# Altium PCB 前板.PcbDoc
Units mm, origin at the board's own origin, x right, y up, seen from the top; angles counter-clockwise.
Board outline 60 x 60 mm, 4 copper layers (Top Layer, GND, PWR, Bottom Layer), stack 0.603 mm thick; 58 components, 58 nets, 327 pads, 79 vias.
Unrouted connection lines stored in the file: 2.
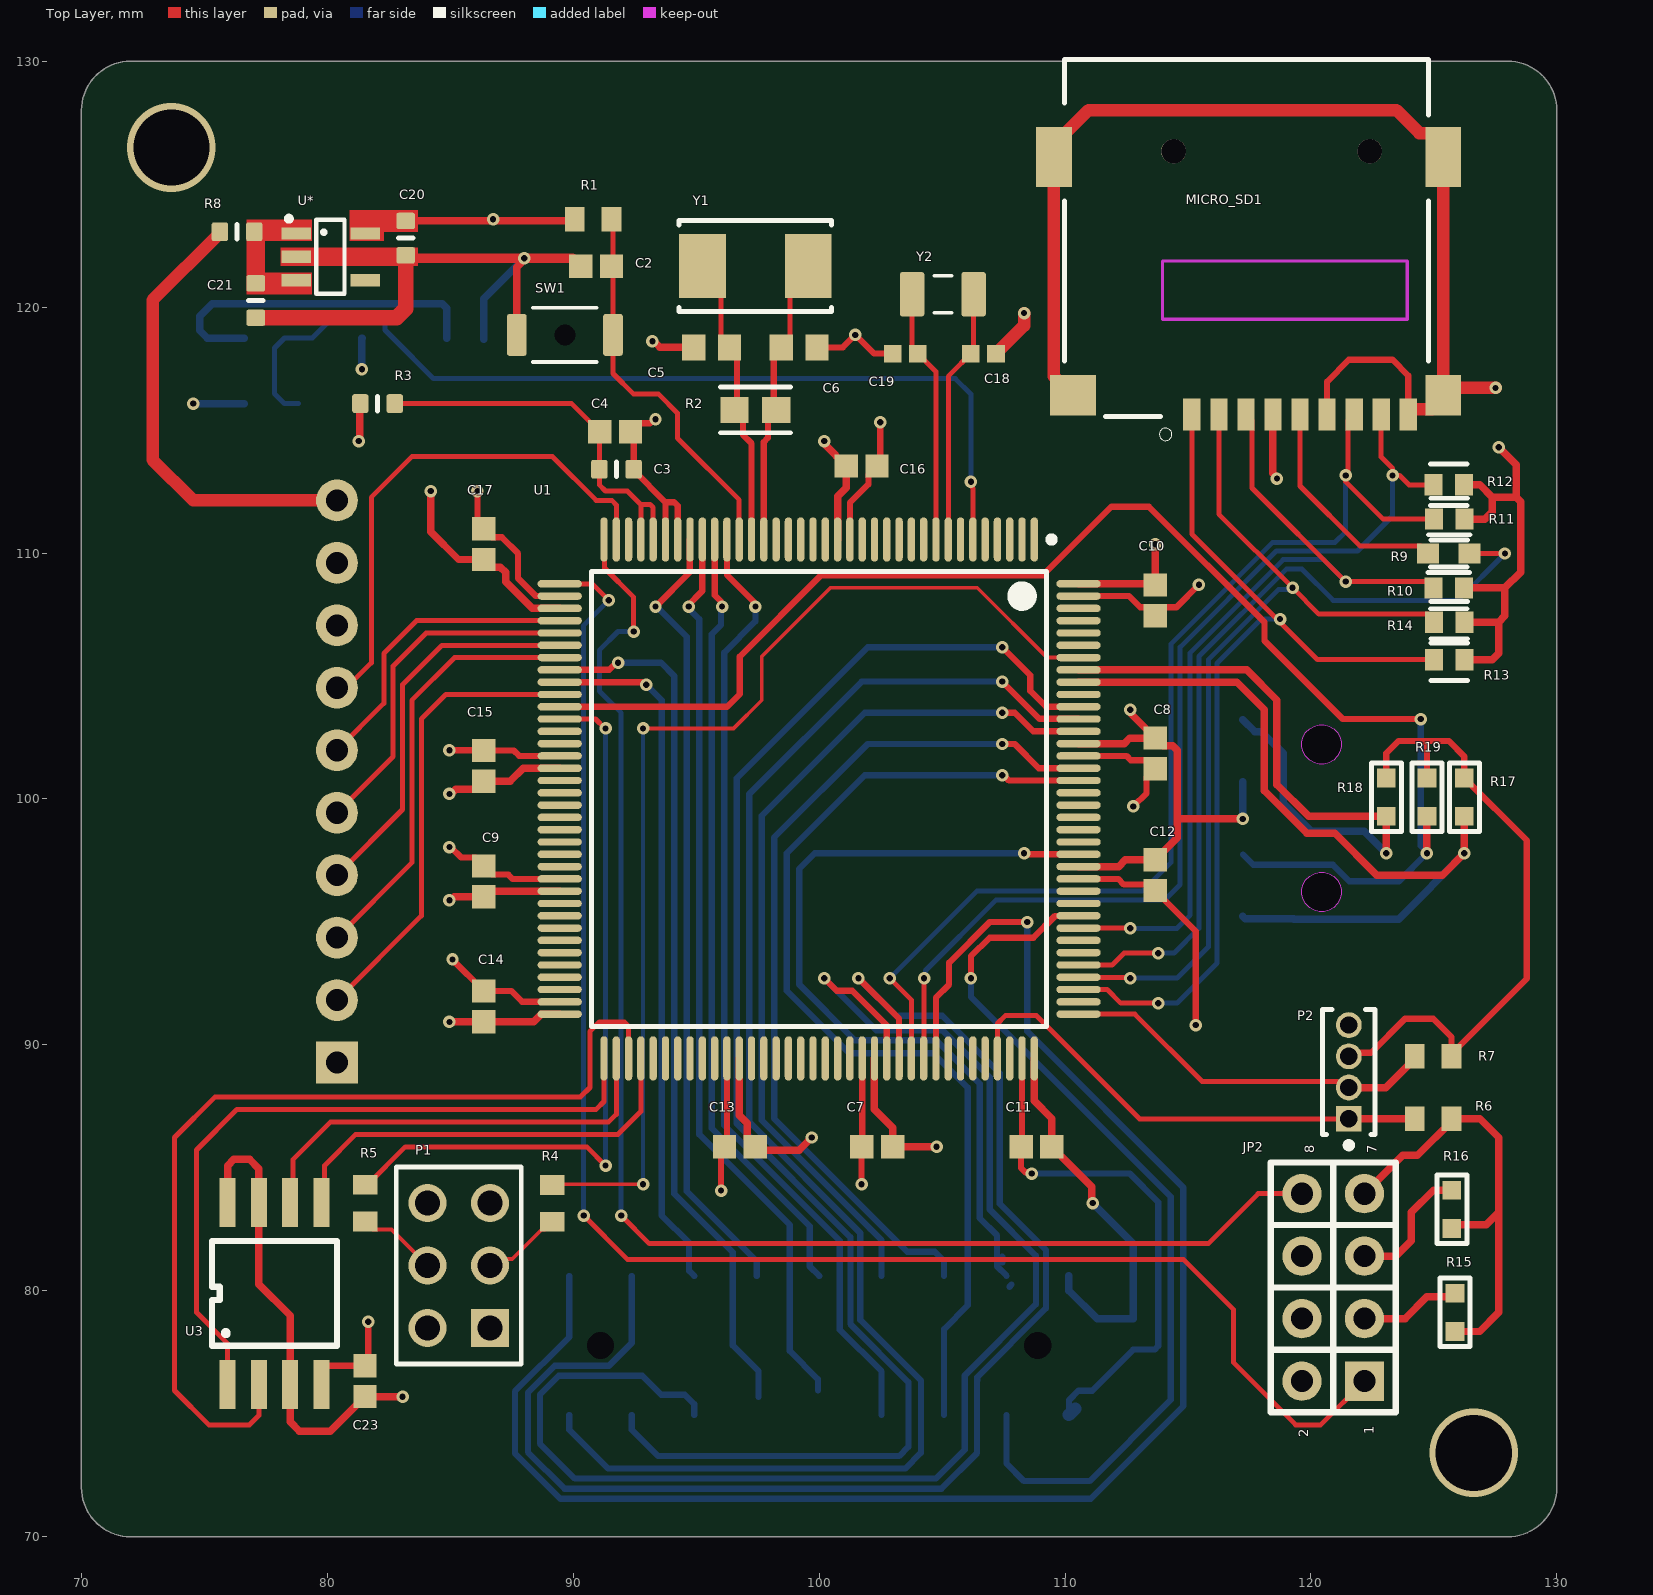
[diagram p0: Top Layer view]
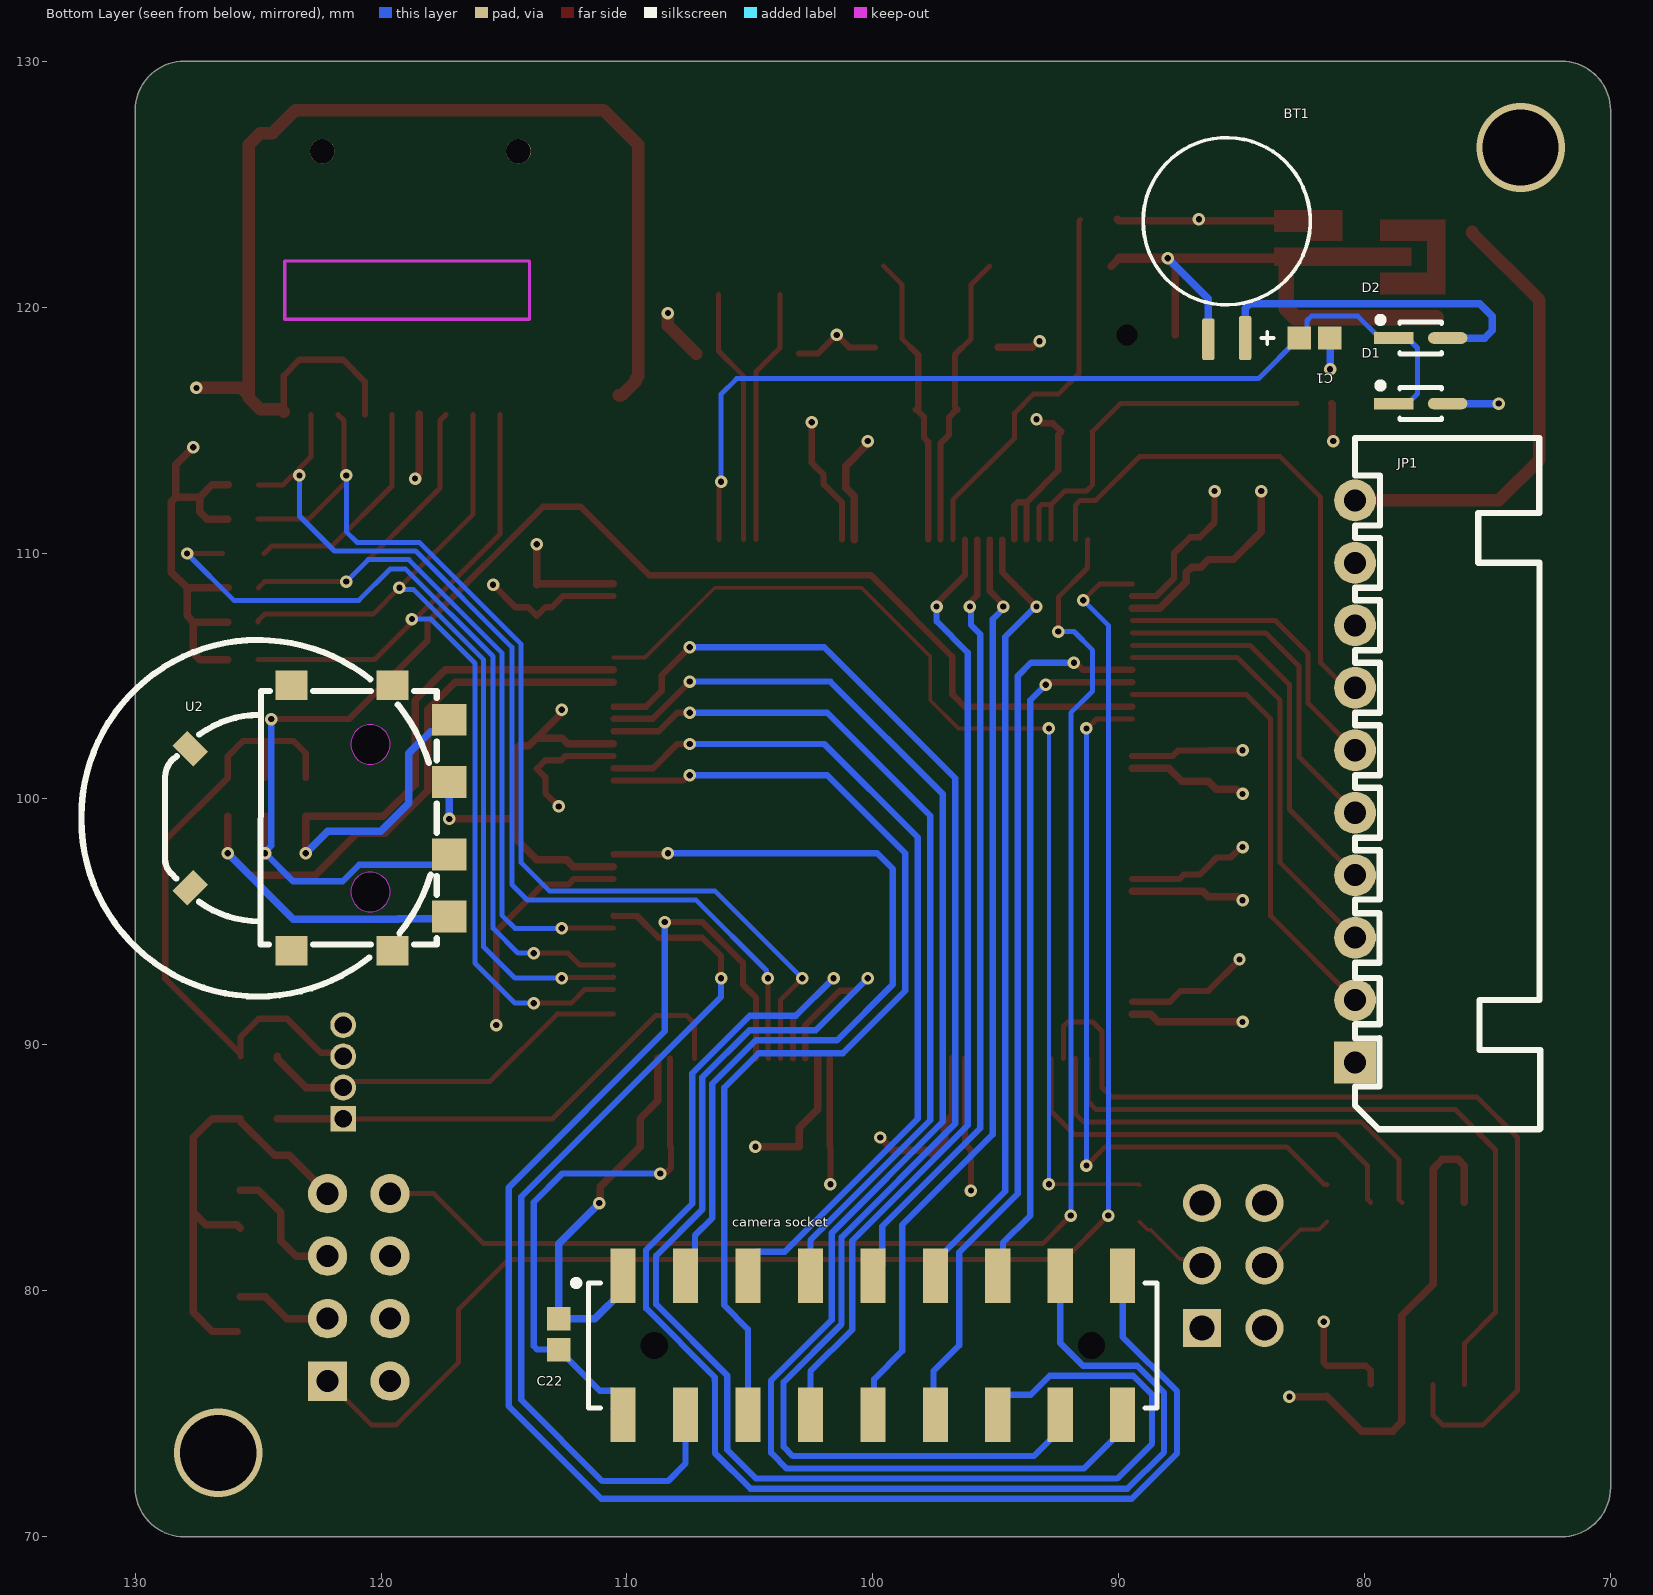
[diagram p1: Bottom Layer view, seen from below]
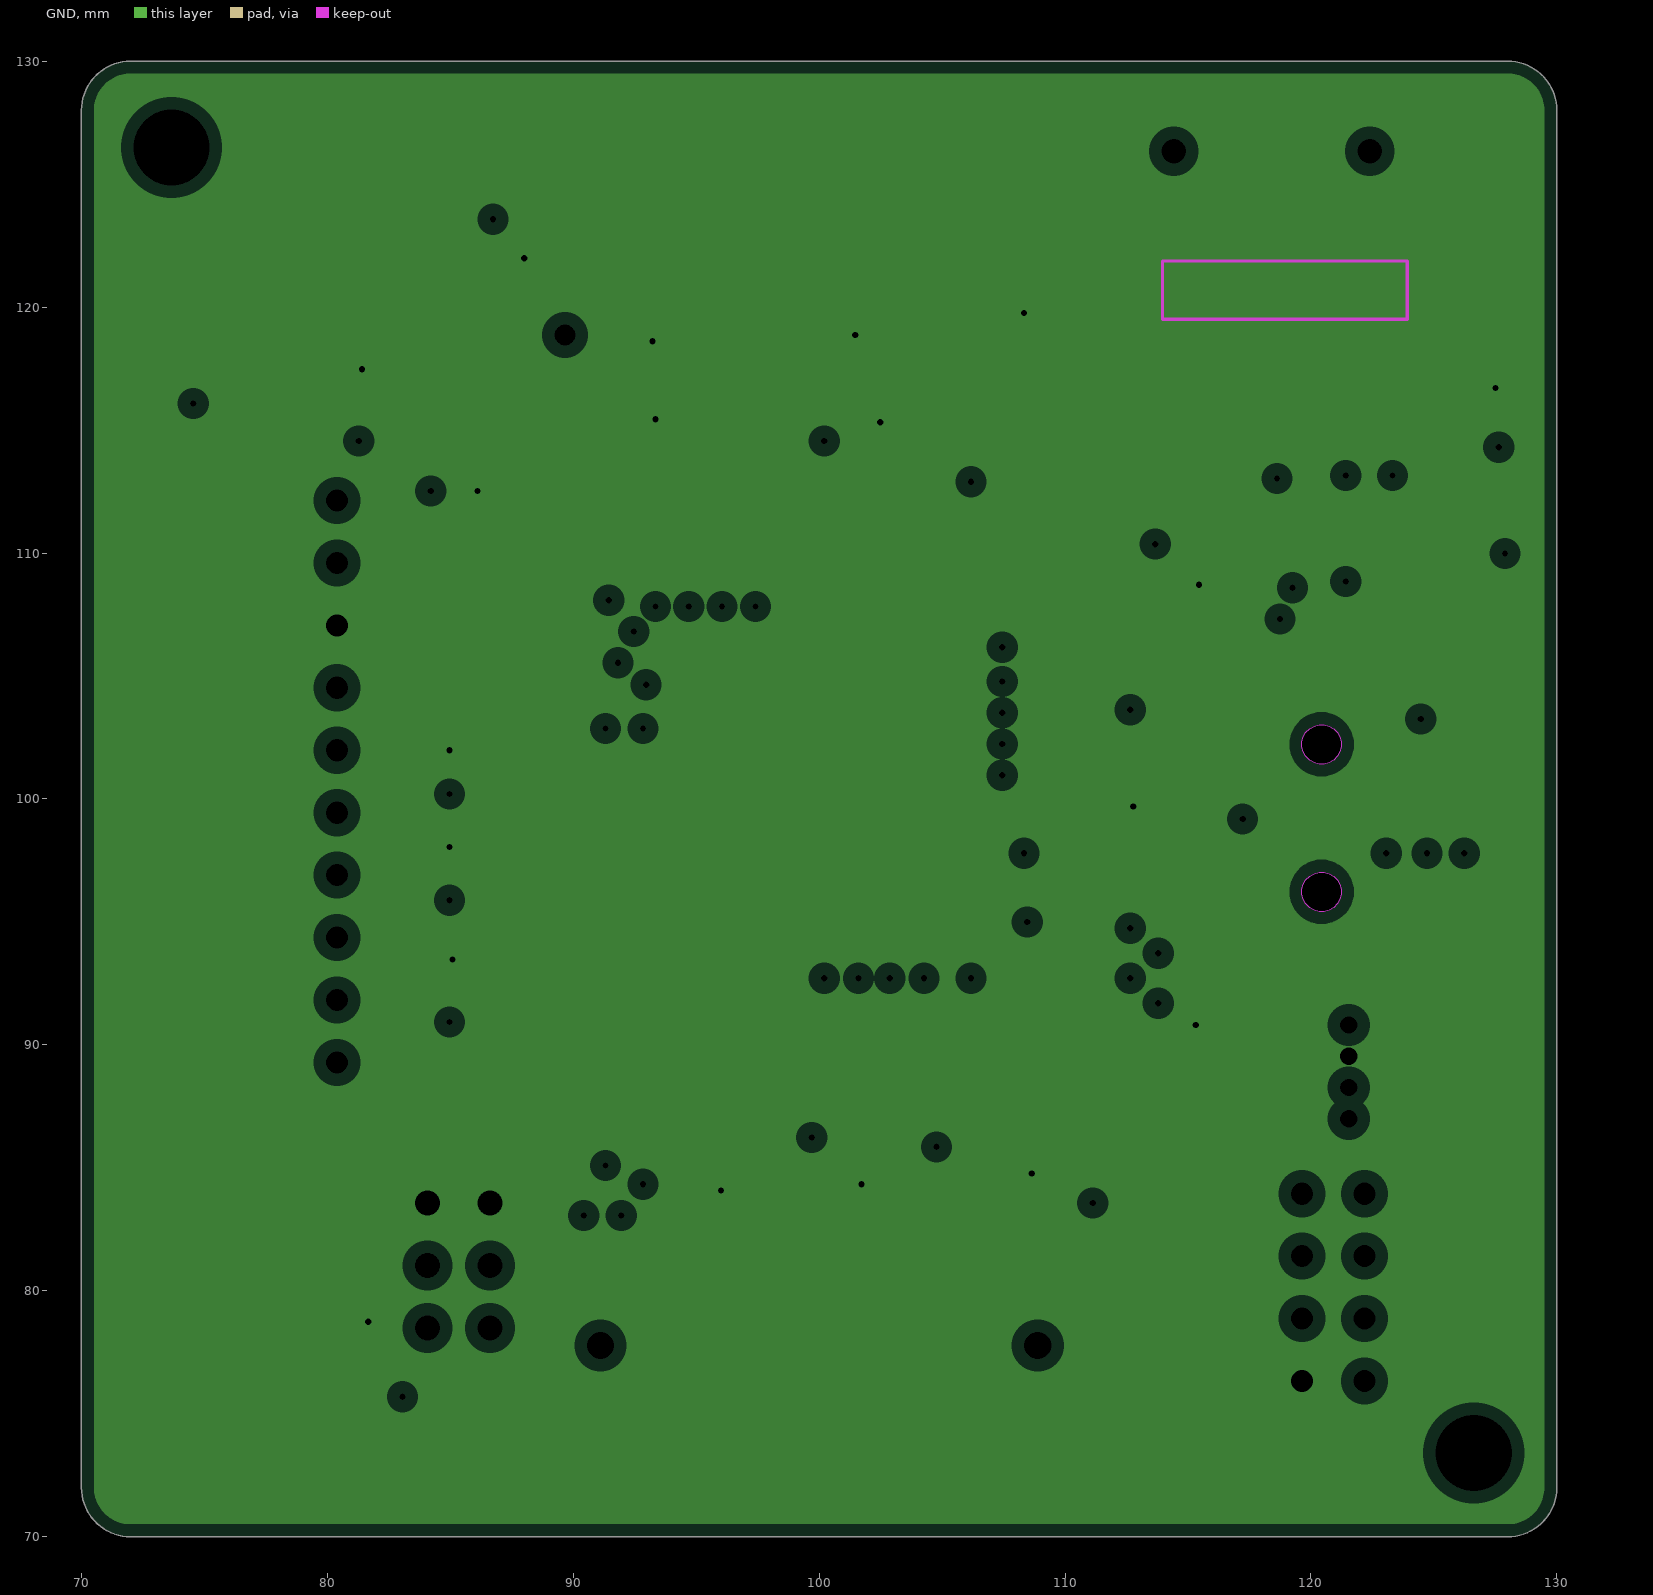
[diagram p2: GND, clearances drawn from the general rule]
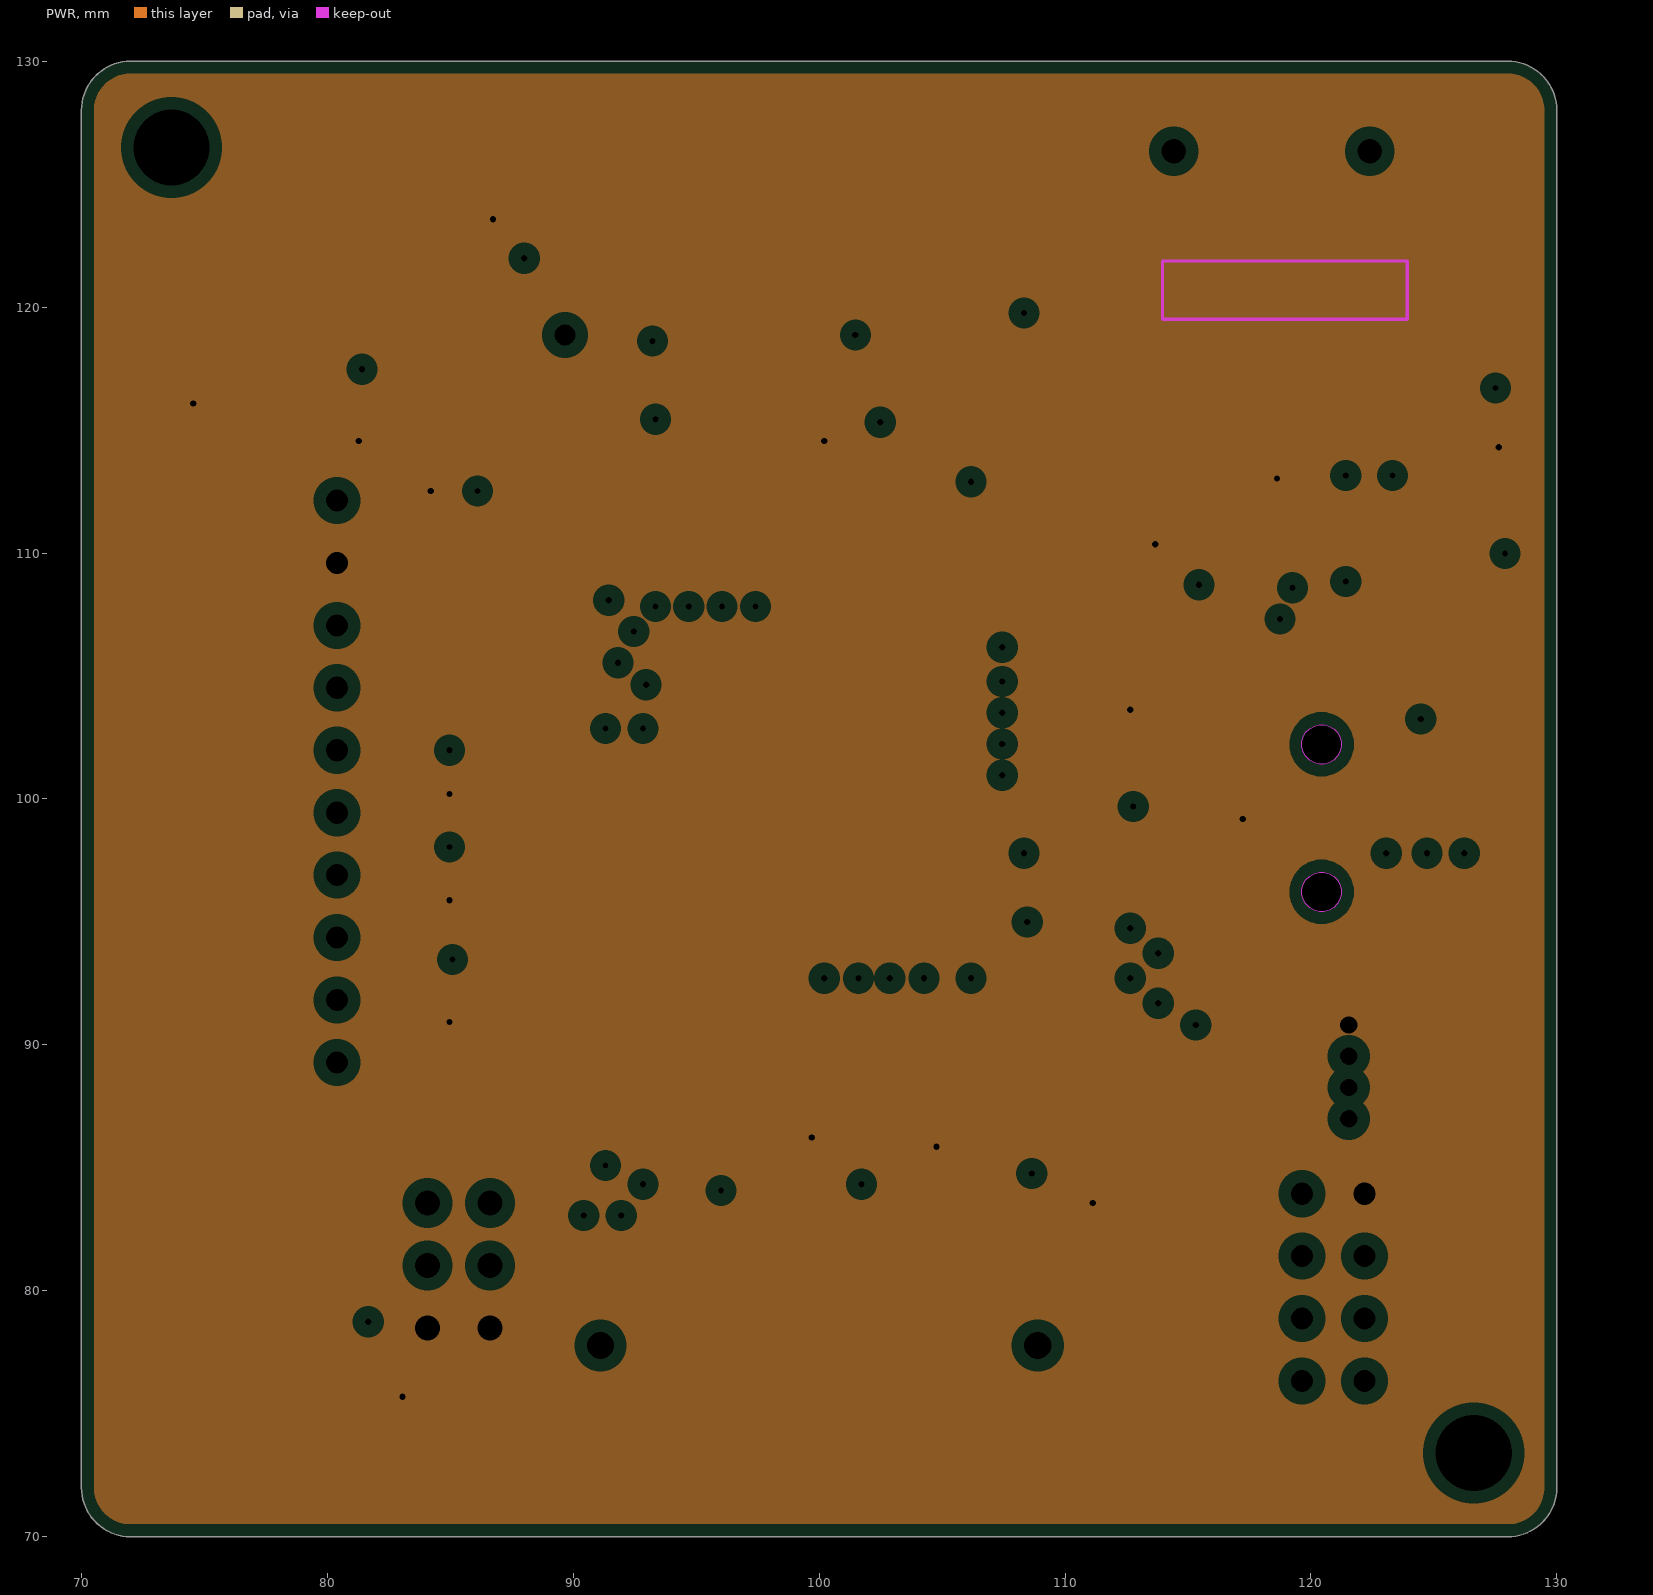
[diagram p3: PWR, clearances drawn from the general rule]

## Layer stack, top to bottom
Top Solder: solder mask 0.0102, Solder Resist, Dk 3.5
Top Layer: signal copper 0.0356
Dielectric 2: prepreg 0.0711, PP-006, Dk 4.1
GND: plane copper 0.035, net GND
Dielectric 1: dielectric 0.32, FR-4, Dk 4.8
PWR: plane copper 0.035, net VCC
Dielectric 3: prepreg 0.0711, PP-006, Dk 4.1
Bottom Layer: signal copper 0.0356
Bottom Solder: solder mask 0.0102, Solder Resist, Dk 3.5

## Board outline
70,72 70,128 cw(c72,128) 72,130 128,130 cw(c128,128) 130,128 130,72 cw(c128,72) 128,70 72,70 cw(c72,72)

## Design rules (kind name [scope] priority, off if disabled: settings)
Clearance Clearance_1 [InNetClass('pwr')] p1: gap=0.254 ignorepadtopadclearanceinfootprint=FALSE except(0.152: Arc-THPad Arc-Via Arc-Hole Track-THPad Track-Via Track-Hole SMDPad-SMDPad SMDPad-THPad SMDPad-Via SMDPad-Hole THPad-THPad THPad-Via THPad-Hole Via-Via Via-Hole Fill-Hole Poly-Hole Region-Hole Text-Hole)
Clearance [All] p2: gap=0.152 ignorepadtopadclearanceinfootprint=FALSE
DiffPairsRouting DiffPair_DiffPairsRouting [InDifferentialPair ('NewDifferentialPair2')] p1: maxlimit=0.254 minlimit=0.254 mostfreqgap=0.254 toplayer_minwidth=0.152 toplayer_maxwidth=0.381 toplayer_prefwidth=0.203 bottomlayer_minwidth=0.152 bottomlayer_maxwidth=0.381 bottomlayer_prefwidth=0.203 maxuncoupledlength=12.7
DiffPairsRouting DiffPair_DiffPairsRouting_1 [InDifferentialPair ('NewDifferentialPair1')] p2 off: maxlimit=0.254 minlimit=0.254 mostfreqgap=0.254 toplayer_minwidth=0.152 toplayer_maxwidth=0.381 toplayer_prefwidth=0.254 bottomlayer_minwidth=0.152 bottomlayer_maxwidth=0.381 bottomlayer_prefwidth=0.254 maxuncoupledlength=12.7
DiffPairsRouting [All] p3: maxlimit=0.254 minlimit=0.254 mostfreqgap=0.254 toplayer_minwidth=0.381 toplayer_maxwidth=0.381 toplayer_prefwidth=0.381 bottomlayer_minwidth=0.381 bottomlayer_maxwidth=0.381 bottomlayer_prefwidth=0.381 maxuncoupledlength=12.7
MatchedLengths DiffPair_MatchedLengths [InDifferentialPair ('NewDifferentialPair2')] p1: tolerance=25.4 checknetsindiffpair=FALSE checkdiffpairvsdiffpair=TRUE checkxsignals=TRUE checkothers=TRUE
MatchedLengths DiffPair_MatchedLengths_1 [InDifferentialPair ('NewDifferentialPair1')] p2: tolerance=25.4 checknetsindiffpair=FALSE checkdiffpairvsdiffpair=TRUE checkxsignals=TRUE checkothers=TRUE
PlaneClearance [All] p1: clearance=0.508
PlaneConnect [All] p1: planeconnectstyle=Relief reliefexpansion=0.508 reliefentries=4 reliefconductorwidth=0.254 reliefairgap=0.254
PolygonConnect [All] p1: connectstyle=Relief reliefconductorwidth=0.254 reliefentries=4 polygonreliefangle="90 Angle" airgapwidth=0.254
RoutingVias [All] p1: holewidth=0.254 width=0.508 viastyle="Through Hole" minholewidth=0.254 minwidth=0.508 maxholewidth=0.711 maxwidth=1.27
SolderMaskExpansion [All] p1: expansion=0.102 istentingtop=FALSE
Width pwr [InNetClass('pwr')] p1: maxlimit=1.27 minlimit=0.254 preferedwidth=0.635
Width [All] p2: maxlimit=12.7 minlimit=0.152 preferedwidth=0.381
27 further rules are at their usual default settings.

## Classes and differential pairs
pad class stm_pad: U1-1 U1-2 U1-3 U1-4 U1-5 U1-6 U1-7 U1-8 U1-9 U1-10 U1-11 U1-12 U1-13 U1-14 U1-15 U1-16 U1-17 U1-18 U1-19 U1-20 U1-21 U1-22 U1-23 U1-24 U1-25 U1-26 U1-27 U1-28 U1-29 U1-30 U1-31 U1-32 U1-33 U1-34 U1-35 U1-36 U1-37 U1-38 U1-39 U1-40 U1-41 U1-42 U1-43 U1-44 U1-45 U1-46 U1-47 U1-48 U1-49 U1-50 U1-51 U1-52 U1-53 U1-54 U1-55 U1-56 U1-57 U1-58 U1-59 U1-60 U1-61 U1-62 U1-63 U1-64 U1-65 U1-66 U1-67 U1-68 U1-69 U1-70 U1-71 U1-72 U1-73 U1-74 U1-75 U1-76 U1-77 U1-78 U1-79 U1-80 U1-81 U1-82 U1-83 U1-84 U1-85 U1-86 U1-87 U1-88 U1-89 U1-90 U1-91 U1-92 U1-93 U1-94 U1-95 U1-96 U1-97 U1-98 U1-99 U1-100 U1-101 U1-102 U1-103 U1-104 U1-105 U1-106 U1-107 U1-108 U1-109 U1-110 U1-111 U1-112 U1-113 U1-114 U1-115 U1-116 U1-117 U1-118 U1-119 U1-120 U1-121 U1-122 U1-123 U1-124 U1-125 U1-126 U1-127 U1-128 U1-129 U1-130 U1-131 U1-132 U1-133 U1-134 U1-135 U1-136 U1-137 U1-138 U1-139 U1-140 U1-141 U1-142 U1-143 U1-144

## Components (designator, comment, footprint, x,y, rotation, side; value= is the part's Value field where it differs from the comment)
BT1 "MS621FE-FL11E" SEIK-MS621FE-FL11E-2_V 85.61,123.495 r270 bottom
C1 "Capacitor 100 nF +/-10% 50 V 0603" CAPC1608X90X40NL10T20 82.042,118.745 r0 bottom value=100nF
C2 "Capacitor 100 nF +/-10% 50 V 0603" CAPC1608X90X40NL10T20 90.932,121.666 r0 top value=100nF
C3 "Capacitor 10µF +/-20% 10V 0603" CAPC0603(1608)100_L 91.759,113.411 r0 top value=10µF
C4 "Capacitor 100 nF +/-10% 50 V 0603" CAPC1608X90X40NL10T20 91.704,114.935 r0 top value=100nF
C5 "GRM1885C1H220JA01D" CAPC1608X90X35ML10T15 95.631,118.364 r0 top value=22pF
C6 "GRM1885C1H220JA01D" CAPC1608X90X35ML10T15 99.187,118.364 r180 top value=22pF
C7 "Capacitor 100 nF +/-10% 50 V 0603" CAPC1608X90X40NL10T20 102.362,85.852 r0 top value=100nF
C8 "Capacitor 100 nF +/-10% 50 V 0603" CAPC1608X90X40NL10T20 113.665,101.854 r90 top value=100nF
C9 "Capacitor 100 nF +/-10% 50 V 0603" CAPC1608X90X40NL10T20 86.36,96.647 r270 top value=100nF
C10 "Capacitor 100 nF +/-10% 50 V 0603" CAPC1608X90X40NL10T20 113.665,108.077 r90 top value=100nF
C11 "Capacitor 100 nF +/-10% 50 V 0603" CAPC1608X90X40NL10T20 108.839,85.852 r0 top value=100nF
C12 "Capacitor 100 nF +/-10% 50 V 0603" CAPC1608X90X40NL10T20 113.665,96.901 r90 top value=100nF
C13 "Capacitor 100 nF +/-10% 50 V 0603" CAPC1608X90X40NL10T20 96.774,85.852 r0 top value=100nF
C14 "Capacitor 100 nF +/-10% 50 V 0603" CAPC1608X90X40NL10T20 86.36,91.567 r270 top value=100nF
C15 "Capacitor 100 nF +/-10% 50 V 0603" CAPC1608X90X40NL10T20 86.36,101.346 r270 top value=100nF
C16 "Capacitor 100 nF +/-10% 50 V 0603" CAPC1608X90X40NL10T20 101.727,113.538 r180 top value=100nF
C17 "Capacitor 100 nF +/-10% 50 V 0603" CAPC1608X90X40NL10T20 86.36,110.363 r270 top value=100nF
C18 "Capacitor 10 pF +/- 5% 50 V 0402" CAPC1005X55X25ML05T05 106.68,118.11 r180 top value=10pF
C19 "Capacitor 10 pF +/- 5% 50 V 0402" CAPC1005X55X25ML05T05 103.505,118.11 r0 top value=10pF
C20 "Capacitor 10µF +/-20% 10V 0603" CAPC0603(1608)100_L 83.185,122.809 r90 top value=10µF
C21 "Capacitor 10µF +/-20% 10V 0603" CAPC0603(1608)100_L 77.089,120.269 r270 top value=10µF
C22 "Capacitor 100 nF +/-10% 50 V 0603" CAPC1608X90X40NL10T20 112.776,78.232 r270 bottom value=100nF
C23 "Capacitor 100 nF +/-10% 50 V 0603" CAPC1608X90X40NL10T20 81.534,76.327 r270 top value=100nF
"camera socket" "SSM-109-S-DV-A" SMTC-SSM-109-X-DV-A 100,77.778 r180 bottom
D1 "1N4148WS" FP-477AB-IPC_A 77.724,116.078 r180 bottom
D2 "1N4148WS" FP-477AB-IPC_A 77.724,118.745 r180 bottom
JP1 "10p" XH2.54-WI-10P 80.391,100.711 r90 bottom
JP2 "2.54排针排母 4X2" HDR2.54-LI-2x4P 120.904,80.137 r90 top
MICRO_SD1 "TF-01A" TF-01A 117.386,122.811 r180 top
P1 "TSW-103-08-T-D" SMTC-TSW-103-08-X-D 86.614,78.486 r90 top
P2 "GRPB041VWVN-RC" SLIN-GRPB041VWVN-RC_V 121.539,88.9 r90 top
R1 "Resistor 10k +/-1% 0603 100 mW" RESC1608X55X25ML10T15 90.805,123.571 r0 top value=10k
R2 "ERJ-3EKF1004V" FP-ERJ3EK-IPC_A 97.409,115.824 r0 top value=1M
R3 "ERJ3EKF10R0V" RESC0603(1608)_L 82.042,116.078 r180 top value=10
R4 "Resistor 10k +/-1% 0603 100 mW" RESC1608X55X25ML10T15 89.154,83.554 r270 top value=10k
R5 "Resistor 10k +/-1% 0603 100 mW" RESC1608X55X25ML10T15 81.534,83.566 r90 top value=10k
R6 "Resistor 10k +/-1% 0603 100 mW" RESC1608X55X25ML10T15 124.968,86.995 r0 top value=10k
R7 "Resistor 10k +/-1% 0603 100 mW" RESC1608X55X25ML10T15 124.968,89.535 r0 top value=10k
R8 "0R3J" RESC0603(1608)_L 76.327,123.063 r0 top value=0
R9 "RC0603JR-07100RL" FP-RC0603-0_55-MFG 125.603,109.982 r180 top value=100
R10 "CRCW060347K0FKEA" FP-CRCW0603-e3-IPC_C 125.603,108.585 r180 top value=47k
R11 "CRCW060347K0FKEA" FP-CRCW0603-e3-IPC_C 125.623,111.379 r180 top value=47k
R12 "CRCW060347K0FKEA" FP-CRCW0603-e3-IPC_C 125.603,112.776 r180 top value=47k
R13 "CRCW060347K0FKEA" FP-CRCW0603-e3-IPC_C 125.623,105.664 r180 top value=47k
R14 "CRCW060347K0FKEA" FP-CRCW0603-e3-IPC_C 125.623,107.188 r180 top value=47k
R15 "10k" "R 0603_L" 125.857,79.121 r90 top
R16 "10k" "R 0603_L" 125.73,83.312 r90 top
R17 "10k" "R 0603_L" 126.238,100.076 r270 top
R18 "10k" "R 0603_L" 123.063,100.076 r90 top
R19 "10k" "R 0603_L" 124.714,100.076 r270 top
SW1 "B3U-1000P-B" OMRON-B3U-1000P-2-B_V 89.662,118.872 r180 top
U1 "STM32F103ZET6" STM-LQFP144_N 100,100 r270 top
U2 "SIQ-02FVS3" SW-SMD_SIQ-02FVS3_1 122.498,99.221 r90 bottom
U3 "W25Q128FVSIG" SOIC-8_208mil 77.978,79.883 r90 top
U* "ME6211C33M5G-N" SOT23-5N 80.137,122.047 r270 top
Y1 "ABM7-8.000MHZ-D2Y-T" FP-ABM7-MFG 97.409,121.666 r0 top
Y2 "ABS07-166-32.768KHZ-T" EPSON-FC-135_V 105.029,120.523 r180 top

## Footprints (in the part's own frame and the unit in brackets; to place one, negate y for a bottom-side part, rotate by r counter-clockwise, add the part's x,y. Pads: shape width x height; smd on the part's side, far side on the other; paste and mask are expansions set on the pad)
CAPC0603(1608)100_L [mm] "Chip Capacitor, Body 1.6x0.8mm, Height 1.0mm, IPC High Density"
  rrect25% 0.66x0.76 smd: 1(-0.7,0) 2(0.7,0)
  silkscreen extent 0,-0.3 0,0.3, body extent -0.8,-0.4 0.8,0.4, height 0.95
CAPC1005X55X25ML05T05 [mm] "Chip Capacitor, 2-Leads, Body 1.05x0.55mm, IPC Low Density"
  rect 0.72x0.72 smd: 1(-0.51,0) 2(0.51,0)
  body extent -0.53,-0.28 0.53,0.28, height 0.55
CAPC1608X90X35ML10T15 [mm] "Chip Capacitor, 2-Leads, Body 1.7x0.9mm, IPC Low Density"
  rect 0.95x1.05 smd: 1(-0.725,0) 2(0.725,0)
  body extent -0.85,-0.45 0.85,0.45, height 0.9
CAPC1608X90X40NL10T20 [mm] "Chip Capacitor, 2-Leads, Body 1.70x0.90mm, IPC Medium Density"
  rect 0.95x0.95 smd: 1(-0.625,0) 2(0.625,0)
  body extent -0.85,-0.45 0.85,0.45, height 0.9
EPSON-FC-135_V [mm] "SMD, 2-Leads, Body 3.2x1.5mm"
  rrect20% 1x1.8 smd: 1(-1.25,0) 2(1.25,0)
  silkscreen extent -0.35,-0.75 0.35,0.75, body extent -1.6,-0.75 1.6,0.75, height 0.9
FP-477AB-IPC_A [mm]
  rect 1.606x0.472 smd paste+0 mask+0: 1(-1.1,0)
  rrect100% 1.606x0.472 smd paste+0 mask+0: 2(1.1,0)
  silkscreen extent -1.76,-0.65 0.85,0.86, body extent -1.25,-0.63 1.25,0.63, height 0.9
FP-ABM7-MFG [mm]
  rect 1.9x2.6 smd paste+0 mask+0: 1(-2.15,0) 2(2.15,0)
  silkscreen extent -3.1,-1.85 3.1,1.85, body extent -3.2,-1.95 3.2,1.95, height 0.25
FP-CRCW0603-e3-IPC_C [mm]
  rect 0.735x0.862 smd paste+0 mask+0: 1(-0.615,0) 2(0.615,0)
  silkscreen extent -0.75,-0.85 0.75,0.85, body extent -0.77,-0.43 0.77,0.43, height 0.5
FP-ERJ3EK-IPC_A [mil]
  rect 45.53x41.82 smd paste+0 mask+0: 1(-33.5,0) 2(33.5,0)
  silkscreen extent -56,-37 56,37, body extent -76,-41 76,41, height 10
FP-RC0603-0_55-MFG [mm]
  rect 0.9x0.8 smd paste+0 mask+0: 1(-0.85,0) 2(0.85,0)
  silkscreen extent -0.87,-0.76 0.85,0.77, body extent -0.8,-0.4 0.8,0.4, height 0.55
HDR2.54-LI-2x4P [mm] "双排排针，4x2脚"
  rect 1.6x1.6 hole 0.9: 1(-3.81,-1.27)
  round 1.6 hole 0.9: 2(-3.81,1.27) 3(-1.27,-1.27) 4(-1.27,1.27) 5(1.27,-1.27) 6(1.27,1.27) 7(3.81,-1.27) 8(3.81,1.27)
  silkscreen extent -5.08,-2.54 5.08,2.54, body extent -5.08,-2.54 5.08,2.54, height 8.5
OMRON-B3U-1000P-2-B_V [mm] "SMT, 2-Leads, Body 3x2.5mm"
  rrect25% 0.8x1.7 smd: 1(-1.954,0) 2(1.954,0)
  round 0 hole 0.85 unplated: H1(0,0)
  silkscreen extent -1.3,-1.1 1.3,1.1, body extent -2,-1.25 2,1.25, height 1.6
"R 0603_L" [mil] "1/10W贴片电阻"
  rect 30x30 smd: 1(-30.59,0) 2(30.59,0)
  silkscreen extent -55,-24 55,24, body extent -31,-16 32,16, height 16
RESC0603(1608)_L [mm] "Chip Resistor, Body 1.6x0.8mm, IPC High Density"
  rrect25% 0.66x0.76 smd: 1(-0.7,0) 2(0.7,0)
  silkscreen extent 0,-0.3 0,0.3, body extent -0.8,-0.4 0.8,0.4, height 0.45
RESC1608X55X25ML10T15 [mm] "Chip Resistor, 2-Leads, Body 1.70x0.90mm, IPC Low Density"
  rect 0.8x1 smd: 1(-0.75,0) 2(0.75,0)
  body extent -0.85,-0.45 0.85,0.45, height 0.55
SEIK-MS621FE-FL11E-2_V [mm] "SMD, 2-Leads, Diameter 6.8mm"
  rrect35% 1.8x0.5 smd: 1(4.75,0.75)
  rrect35% 1.7x0.5 smd: 2(4.8,-0.75)
  silkscreen extent -3.4,-3.4 5,3.4, body extent -3.4,-3.4 4.35,3.4, height 2.7
SLIN-GRPB041VWVN-RC_V [mm] "Header, 4-Leads, Body 5.08x2.14mm, Pitch 1.27mm"
  rect 1.05x1.05 hole 0.7: 1(-1.905,0)
  round 1.05 hole 0.7: 2(-0.635,0) 3(0.635,0) 4(1.905,0)
  silkscreen extent -3.1,-1.07 2.54,1.07, body extent -2.54,-1.07 2.54,1.07, height 4
SMTC-SSM-109-X-DV-A [mm] "C.L. Double Vertical SMT Socket Strip, 2x9 Pins, 2.54mm Pitch, Female"
  rect 1.02x2.22 smd: 1(-10.16,2.825) 2(-10.16,-2.825) 3(-7.62,2.825) 4(-7.62,-2.825) 5(-5.08,2.825) 6(-5.08,-2.825) 7(-2.54,2.825) 8(-2.54,-2.825) 9(0,2.825) 10(0,-2.825) 11(2.54,2.825) 12(2.54,-2.825) 13(5.08,2.825) 14(5.08,-2.825) 15(7.62,2.825) 16(7.62,-2.825) 17(10.16,2.825) 18(10.16,-2.825)
  round 0.8 hole 1.1 unplated: MH1(-8.89,0) MH2(8.89,0)
  silkscreen extent -12.19,-2.54 11.56,2.66, body extent -11.43,-3.52 11.43,3.52, height 7.42
SMTC-TSW-103-08-X-D [mm] ".025 SQ Post Terminal Strip Assembly, 2x3 Pins, Vertical, 2.54mm Pitch, Male"
  rect 1.55x1.55 hole 1.02: 1(0,0)
  round 1.55 hole 1.02: 2(0,2.54) 3(2.54,0) 4(2.54,2.54) 5(5.08,0) 6(5.08,2.54)
  silkscreen extent -1.46,-1.27 6.54,3.81, body extent -1.27,-1.27 6.35,3.81, height 8.38
SOIC-8_208mil [mm]
  rect 2x0.65 smd: 1(-3.688,2.032) 2(-3.688,0.762) 3(-3.688,-0.508) 4(-3.688,-1.778) 5(3.712,-1.778) 6(3.712,-0.508) 7(3.712,0.762) 8(3.712,2.032)
  silkscreen extent -2.12,-2.41 2.14,2.67, body extent -4.2,-2.56 4.2,2.82, height 2.3
SOT23-5N [mm] "3x1.6x1.1mm(长宽高)"
  rect 0.5x1.2 smd: 1(-0.95,-1.4) 2(0,-1.4) 3(0.95,-1.4) 4(0.95,1.4) 5(-0.95,1.4)
  silkscreen extent -1.63,-1.78 1.5,0.56, body extent -1.5,-1.4 1.5,1.4, height 1.15
STM-LQFP144_N [mm] "Thin QFP, 144-Leads, Body 20x20mm, Pitch 0.5mm, IPC Medium Density"
  oval 1.8x0.3 smd: 1(-10.55,8.75) 2(-10.55,8.25) 3(-10.55,7.75) 4(-10.55,7.25) 5(-10.55,6.75) 6(-10.55,6.25) 7(-10.55,5.75) 8(-10.55,5.25) 9(-10.55,4.75) 10(-10.55,4.25) 11(-10.55,3.75) 12(-10.55,3.25) 13(-10.55,2.75) 14(-10.55,2.25) 15(-10.55,1.75) 16(-10.55,1.25) 17(-10.55,0.75) 18(-10.55,0.25) 19(-10.55,-0.25) 20(-10.55,-0.75) 21(-10.55,-1.25) 22(-10.55,-1.75) 23(-10.55,-2.25) 24(-10.55,-2.75) 25(-10.55,-3.25) 26(-10.55,-3.75) 27(-10.55,-4.25) 28(-10.55,-4.75) 29(-10.55,-5.25) 30(-10.55,-5.75) 31(-10.55,-6.25) 32(-10.55,-6.75) 33(-10.55,-7.25) 34(-10.55,-7.75) 35(-10.55,-8.25) 36(-10.55,-8.75) 73(10.55,-8.75) 74(10.55,-8.25) 75(10.55,-7.75) 76(10.55,-7.25) 77(10.55,-6.75) 78(10.55,-6.25) 79(10.55,-5.75) 80(10.55,-5.25) 81(10.55,-4.75) 82(10.55,-4.25) 83(10.55,-3.75) 84(10.55,-3.25) 85(10.55,-2.75) 86(10.55,-2.25) 87(10.55,-1.75) 88(10.55,-1.25) 89(10.55,-0.75) 90(10.55,-0.25) 91(10.55,0.25) 92(10.55,0.75) 93(10.55,1.25) 94(10.55,1.75) 95(10.55,2.25) 96(10.55,2.75) 97(10.55,3.25) 98(10.55,3.75) 99(10.55,4.25) 100(10.55,4.75) 101(10.55,5.25) 102(10.55,5.75) 103(10.55,6.25) 104(10.55,6.75) 105(10.55,7.25) 106(10.55,7.75) 107(10.55,8.25) 108(10.55,8.75)
  oval 0.3x1.8 smd: 37(-8.75,-10.55) 38(-8.25,-10.55) 39(-7.75,-10.55) 40(-7.25,-10.55) 41(-6.75,-10.55) 42(-6.25,-10.55) 43(-5.75,-10.55) 44(-5.25,-10.55) 45(-4.75,-10.55) 46(-4.25,-10.55) 47(-3.75,-10.55) 48(-3.25,-10.55) 49(-2.75,-10.55) 50(-2.25,-10.55) 51(-1.75,-10.55) 52(-1.25,-10.55) 53(-0.75,-10.55) 54(-0.25,-10.55) 55(0.25,-10.55) 56(0.75,-10.55) 57(1.25,-10.55) 58(1.75,-10.55) 59(2.25,-10.55) 60(2.75,-10.55) 61(3.25,-10.55) 62(3.75,-10.55) 63(4.25,-10.55) 64(4.75,-10.55) 65(5.25,-10.55) 66(5.75,-10.55) 67(6.25,-10.55) 68(6.75,-10.55) 69(7.25,-10.55) 70(7.75,-10.55) 71(8.25,-10.55) 72(8.75,-10.55) 109(8.75,10.55) 110(8.25,10.55) 111(7.75,10.55) 112(7.25,10.55) 113(6.75,10.55) 114(6.25,10.55) 115(5.75,10.55) 116(5.25,10.55) 117(4.75,10.55) 118(4.25,10.55) 119(3.75,10.55) 120(3.25,10.55) 121(2.75,10.55) 122(2.25,10.55) 123(1.75,10.55) 124(1.25,10.55) 125(0.75,10.55) 126(0.25,10.55) 127(-0.25,10.55) 128(-0.75,10.55) 129(-1.25,10.55) 130(-1.75,10.55) 131(-2.25,10.55) 132(-2.75,10.55) 133(-3.25,10.55) 134(-3.75,10.55) 135(-4.25,10.55) 136(-4.75,10.55) 137(-5.25,10.55) 138(-5.75,10.55) 139(-6.25,10.55) 140(-6.75,10.55) 141(-7.25,10.55) 142(-7.75,10.55) 143(-8.25,10.55) 144(-8.75,10.55)
  silkscreen extent -10.67,-9.25 9.25,9.58, body extent -10,-10 10,10, height 1.6
SW-SMD_SIQ-02FVS3_1 [mm]
  rect 1.2x1.3 smd paste+0 mask+0.05: 1(5.4,-2.964) 2(5.4,1.136) 5(-5.4,1.136) 6(-5.4,-2.964)
  rect 0.85x1.2 smd rot 135 paste+0 mask+0.05: 3(2.828,5.264)
  rect 0.85x1.2 smd rot 45 paste+0 mask+0.05: 4(-2.828,5.264)
  rect 1.3x1.4 smd paste+0 mask+0.05: A(-4,-5.264) B(4,-5.264) C(1.475,-5.264) S(-1.475,-5.264)
  Keep-Out Layer board cut-out: 3.8,-2.064 3.8,-1.959 3.745,-1.755 3.64,-1.573 3.491,-1.424 3.309,-1.319 3.105,-1.264 2.895,-1.264 2.691,-1.319 2.509,-1.424 2.36,-1.573 2.255,-1.755 2.2,-1.959 2.2,-2.064 2.2,-2.17 2.255,-2.373 2.36,-2.555 2.509,-2.704 2.691,-2.81 2.895,-2.864 3.105,-2.864 3.309,-2.81 3.491,-2.704 3.64,-2.555 3.745,-2.373 3.8,-2.17 3.8,-2.064 3.8,-2.064
  Keep-Out Layer board cut-out: -2.2,-2.064 -2.2,-1.959 -2.255,-1.755 -2.36,-1.573 -2.509,-1.424 -2.691,-1.319 -2.895,-1.264 -3.105,-1.264 -3.309,-1.319 -3.491,-1.424 -3.64,-1.573 -3.745,-1.755 -3.8,-1.959 -3.8,-2.064 -3.8,-2.17 -3.745,-2.373 -3.64,-2.555 -3.491,-2.704 -3.309,-2.81 -3.105,-2.864 -2.895,-2.864 -2.691,-2.81 -2.509,-2.704 -2.36,-2.555 -2.255,-2.373 -2.2,-2.17 -2.2,-2.064 -2.2,-2.064
  silkscreen extent -7.25,-4.76 7.25,9.69
TF-01A [mm]
  rect 0.7x1.3 smd: 1(2.23,7.174) 2(1.13,7.174) 3(0.03,7.174) 4(-1.07,7.174) 5(-2.17,7.174) 6(-3.27,7.174) 7(-4.37,7.174) 8(-5.47,7.174) CD1(-6.57,7.174)
  rect 1.448x1.651 smd: MP1(-7.989,6.4)
  rect 1.448x2.438 smd: MP2(-7.989,-3.3) MP3(7.836,-3.3)
  rect 1.854x1.651 smd: MP4(7.061,6.4)
  round 1 hole 1 unplated: ""(-5.004,-3.531) ""(2.972,-3.531)
  Keep-Out Layer lines w0.127: 3.429,3.302 3.429,0.94 -6.528,0.94 -6.528,3.302 3.429,3.302
  silkscreen extent -7.4,-7.26 7.4,8.24, body extent -8.05,-7.54 8.05,7.66, height 2
XH2.54-WI-10P [mm] "接插件，10P"
  rect 1.7x1.7 hole 0.9: 1(-11.43,0)
  round 1.7 hole 0.9: 2(-8.89,0) 3(-6.35,0) 4(-3.81,0) 5(-1.27,0) 6(1.27,0) 7(3.81,0) 8(6.35,0) 9(8.89,0) 10(11.43,0)
  silkscreen extent -14.15,-7.53 13.97,0, body extent -13.93,-7.35 13.93,0.35, height 5.73

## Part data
BT1: library part CMP-00029-00000-1, "MS Lihium Rechargeable Battery, 3 V, -20 to 60 degC, Tray"
C1 C2 C4 C7 C8 C9 C10 C11 C12 C13 C14 C15 C16 C17 C22 C23: library part CMP-001-00017-6, "Chip Capacitor, 100 nF, +/- 10%, 50 V, 0603 (1608 Metric)", Capacitor Type=Ceramic, Case/Package=0603, Max Operating Temperature=125°C, Min Operating Temperature=-55°C, Tolerance=10%, Voltage Rating=50V
C3 C20 C21: library part CMP-001-00075-4, "Chip Capacitor, 10µF +/-20%, 10V, 0603, Thickness 1 mm", Case/Package=0603, Max Operating Temperature=85°C, Min Operating Temperature=-55°C, Tolerance=10%, Voltage Rating=10V
C5 C6: library part CMP-001-00089-1, "CAP CER 22PF 50V C0G/NP0 0603", Case/Package=0603, Max Operating Temperature=125°C, Min Operating Temperature=-55°C, Tolerance=10%, Voltage Rating=50V
C18 C19: library part CMP-001-00013-6, "Chip Capacitor, 10 pF, +/- 5%, 50 V, 0402 (1005 Metric)", Capacitor Type=Ceramic, Case/Package=0402, Max Operating Temperature=125°C, Min Operating Temperature=-55°C, Tolerance=5%, Voltage Rating=50V
"camera socket": library part CMP-00012-1, "Headers & Wire Housings Surface Mount PCB Socket Strips, 0.100 pitch"
D1 D2: library part CMP-004-00033-1, "Diode Ultra Fast Recovery Rectifier 75V 0.15A 2-Pin SOD-323F T/R", Forward Current=150mA, Forward Voltage=1V, Max Operating Temperature=150°C, Min Operating Temperature=-55°C
JP1: library part CMP-069-000000-1
JP2: library part CMP-002-00115-2, "4*2P接插件"
MICRO_SD1: library part CMP-041-000000-2, "Standard Card Edge Connectors", Package=Package
P1: library part CMP-00008-1, "Headers & Wire Housings Classic PCB Header Strips, 0.100 pitch"
P2: library part CMP-00010-1, "Male, 4 C, Straight, .050\" CC; 3.00mm Head/2.30mm Tail, No Mt; Nylon 9T, Brass, 105 C"
R1 R4 R5 R6 R7: library part CMP-009-00017-5, "Chip Resistor, 10 KOhm, +/- 1%, 01 W, -55 to 155 degC, 0603 (1608 Metric)", Case/Package=0603, Max Operating Temperature=155°C, Min Operating Temperature=-55°C, Power=100mW, Tolerance=1%, Voltage Rating=50V
R2: library part CMP-009-00178-1, "Res Thick Film 0603 1M Ohm 1% 1/10W ±100ppm/°C Molded SMD Punched Carrier T/R", Case/Package=0603, Max Operating Temperature=155°C, Min Operating Temperature=-55°C, Tolerance=1%, Voltage Rating=75V
R3: library part CMP-009-00179-1, "Res Thick Film 0603 10 Ohm 1% 0.1W(1/10W) +/-100ppm/C Molded SMD Automotive Punched T/R", Case/Package=0603, Max Operating Temperature=155°C, Min Operating Temperature=-55°C, Tolerance=1%, Voltage Rating=75V
R8: library part CMP-009-00063-2, "Jumper 0603 (1608 Metric)", Case/Package=0603
R9: library part CMP-009-00182-1, "Res Thick Film 0603 100 Ohm 5% 1/10W ±100ppm/°C Molded SMD SMD Paper T/R", Case/Package=0603, Max Operating Temperature=155°C, Min Operating Temperature=-55°C, Tolerance=5%, Voltage Rating=50V
R10 R11 R12 R13 R14: library part CMP-009-00184-1, "SMD Chip Resistor, 47 kOhm, ± 1%, 100 mW, 0603 [1608 Metric], Thick Film, General Purpose", Case/Package=0603, Max Operating Temperature=155°C, Min Operating Temperature=-55°C, Tolerance=1%, Voltage Rating=75V
R15 R16 R17 R18 R19: library part CMP-009-00185-1, "贴片电阻"
SW1: library part CMP-011-00011-4, "Ultra-small Surface-mounting Tactile Switches with High Contact Reliability, SPST-NO, -25 to 70 degC, 2-Pin SMD, RoHS, Tape and Reel", Current Rating=50mA, Voltage Rating=12V
U1: library part CMP-020-00025-1, "MCU 32-bit STM32F1 ARM Cortex M3 RISC 512KB Flash 2.5V/3.3V 144-Pin LQFP Tray", Case/Package=LQFP, Clock Frequency=72MHz, Max Operating Temperature=85°C, Max Supply Voltage=3.6V, Min Operating Temperature=-40°C, Min Supply Voltage=2V
U2: library part CMP-043-000000-1, JLCPCB Part Class="Extended Part", LCSC Part Name=拨轮滚轮旋转编码器开关, Manufacturer=MITSUMI(美上美)
U3: library part CMP-019-00053-2, "IC FLASH 128MBIT 104MHZ 8SOIC", Case/Package=SOIC, Frequency=104MHz, Max Operating Temperature=85°C, Max Supply Voltage=3.6V, Min Operating Temperature=-40°C, Min Supply Voltage=2.7V
U*: library part CMP-019-00052-1, "VIN=6.5V Vo=3.3V Io=600mA"
Y1: library part CMP-003-00030-1, "Crystal 8MHz ±20ppm (Tol) ±30ppm (Stability) 18pF FUND 100Ohm 2-Pin Mini-CSMD T/R", Case/Package=CSMD, Frequency=8MHz, Load Capacitance=18pF, Max Operating Temperature=85°C, Min Operating Temperature=-40°C
Y2: library part CMP-003-00029-1, "Crystal 32.768kHz 10ppm 7pF -40C +85C", Frequency=32.768kHz

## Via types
v1: diameter 0.508, hole 0.254, Top Layer to Bottom Layer, 77 vias
v2: diameter 3.6, hole 3.1, Top Layer to Bottom Layer, 2 vias

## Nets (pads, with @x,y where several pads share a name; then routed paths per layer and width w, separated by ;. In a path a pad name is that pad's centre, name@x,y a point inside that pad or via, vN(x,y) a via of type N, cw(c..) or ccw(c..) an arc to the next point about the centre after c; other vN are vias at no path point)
4v7in: JP1.10 R8.1 | length 18.6
  Top Layer w0.508: R8.1 75.627,123.013 72.898,120.284 72.898,113.792 74.549,112.141 JP1.10
BOOT0: R4.1 U1.138 | length 44.5
  Top Layer w0.152: R4.1 89.178,84.328 v1(92.837,84.328) ; v1(92.837,102.87) 96.52,102.87 97.663,104.013 97.663,105.791 100.457,108.585 106.426,108.585 109.261,105.75 U1.138
  Bottom Layer w0.152: v1(92.837,84.328) v1(92.837,102.87)
BOOT1: R5.2 U1.48 | length 30.5
  Top Layer w0.203: R5.2 81.634,84.316 83.17,85.852 90.551,85.852 v1(91.313,85.09) ; U1.48 U1.48 90.904,103.251 91.285,102.87 v1(91.313,102.87)
  Bottom Layer w0.203: v1(91.313,85.09) v1(91.313,102.87)
ENCODER_A: R17.2 U1.136 U2.A | length 32.9
  Top Layer w0.305: U1.136 116.992,104.75 118.11,103.632 118.11,100.33 119.824,98.616 120.967,98.616 122.682,96.901 125.349,96.901 v1(126.238,97.79) R17.2
  Bottom Layer w0.305: U2.A 117.332,95.123 119.294,95.123 119.301,95.116 123.564,95.116 v1(126.238,97.79)
ENCODER_B: R18.1 U1.137 U2.B | length 27.8
  Top Layer w0.305: U1.137 117.381,105.25 118.618,104.013 118.618,100.584 119.903,99.299 R18.1 v1(123.063,97.79)
  Bottom Layer w0.305: U2.B 117.712,102.743 117.983,102.743 118.872,101.854 118.872,99.822 120.015,98.679 122.174,98.679 v1(123.063,97.79)
ENCODER_S: R19.2 U1.47 U2.S | length 58.8
  Top Layer w0.254: U1.47 96.257,103.75 96.774,104.267 96.774,105.791 100.076,109.093 109.093,109.093 111.887,111.887 113.411,111.887 118.11,107.188 118.11,106.426 121.285,103.251 v1(124.46,103.251)
  Top Layer w0.305: v1(124.714,97.79) R19.2
  Bottom Layer w0.254: U2.S 117.654,97.326 120.891,97.326 121.561,96.656 123.58,96.656 v1(124.714,97.79) 124.714,97.845 124.46,98.099 v1(124.46,103.251)
FLASH_CS: U1.73 U3.1 | length 29.2
  Top Layer w0.203: U3.1 75.946,77.851 74.676,79.121 74.676,85.725 76.327,87.376 90.932,87.376 91.25,87.694 U1.73
FLASH_MISO: U1.75 U3.2 | length 38.8
  Top Layer w0.203: U3.2 77.216,74.93 76.835,74.549 75.184,74.549 73.787,75.946 73.787,86.233 75.438,87.884 90.297,87.884 90.678,88.265 90.678,90.551 91.059,90.932 92.075,90.932 92.25,90.757 U1.75
FLASH_MOSI: U1.76 U3.5 | length 17.5
  Top Layer w0.203: U3.5 79.883,83.722 79.883,85.09 81.153,86.36 91.821,86.36 92.75,87.289 U1.76
FLASH_SCK: U1.74 U3.6 | length 18
  Top Layer w0.203: U3.6 78.613,83.722 78.613,85.344 80.137,86.868 91.44,86.868 91.75,87.178 U1.74
GND: "camera socket.2" BT1.2 C1.1 C2.1 C3.2 C4.2 C5.1 C6.1 C7.1 C8.1 C9.1 C10.1 C11.1 C12.1 C13.1 C14.1 C15.1 C16.1 C17.1 C18.1 C19.1 C20.1 C21.2 C22.2 C23.1 JP1.8 JP2.2 MICRO_SD1.6 MICRO_SD1.CD1 MICRO_SD1.MP1 MICRO_SD1.MP2 MICRO_SD1.MP3 MICRO_SD1.MP4 P1.5 P1.6 P2.3 R7.2 R17.1 R18.2 R19.1 SW1.2 U1.16 U1.30 U1.31 U1.38 U1.51 U1.61 U1.71 U1.83 U1.94 U1.107 U1.120 U1.130 U1.143 U3.4 U*.2 | length 198.6
  Top Layer w0.254: U3.4 79.756,76.754 79.954,76.952 C23.1 81.661,77.079 v1(81.661,78.74) ; v1(84.963,98.044) 85.013,98.044 85.437,97.62 86.012,97.62 C9.1 86.708,96.924 87.353,96.924 87.527,96.75 U1.61 ; v1(84.963,101.981) 86.35,101.981 C15.1 87.587,101.971 87.808,101.75 U1.51 ; v1(85.09,93.472) 85.09,93.462 C14.1 87.477,92.192 87.919,91.75 U1.71 ; v1(86.106,112.522) 86.106,111.242 86.708,110.64 87.099,110.64 87.757,109.982 87.757,108.966 88.464,108.259 89.441,108.259 U1.38 ; v1(93.345,115.443) 93.276,115.443 93.116,115.283 92.677,115.283 C4.2 92.459,114.805 C3.2 92.459,113.361 93.75,112.07 ; U1.31 93.75,112.07 ; U1.30 94.25,111.921 94.101,112.07 93.75,112.07 ; v1(96.012,84.074) 96.012,85.715 C13.1 96.25,85.953 U1.83 ; C6.1 100.965,118.364 v1(101.473,118.872) 102.235,118.11 C19.1 ; U1.16 101.25,112.045 102.004,112.799 102.004,113.19 C16.1 102.489,113.675 v1(102.489,115.316) ; v1(101.727,84.328) 101.727,85.842 C7.1 101.75,85.865 U1.94 ; U1.107 108.25,85.888 108.204,85.842 108.204,85.002 108.389,84.817 108.596,84.817 v1(108.645,84.769) ; U1.120 112.165,96.75 112.395,96.52 113.421,96.52 115.316,94.625 v1(115.316,90.805) ; U1.130 112.499,101.75 112.672,101.577 113.317,101.577 C8.1 113.317,100.881 113.317,100.236 v1(112.776,99.695) ; U1.143 112.603,108.25 113.053,107.8 113.317,107.8 C10.1 114.013,107.8 114.531,107.8 v1(115.443,108.712) ; MICRO_SD1.6 120.656,116.973 121.539,117.856 123.317,117.856 123.956,117.217 MICRO_SD1.CD1@123.956,115.743 ; P2.3 121.683,89.679 122.445,89.679 123.825,91.059 124.968,91.059 125.718,90.309 R7.2@125.718,89.635 ; R18.2 123.063,101.854 123.571,102.362 124.587,102.362 ; R19.1 124.714,102.235 124.587,102.362 ; R7.2 R7.2@125.718,89.635 ; 124.587,102.362 125.603,102.362 126.238,101.727 R17.1 128.778,98.313 128.778,92.695 R7.2@125.718,89.635
  Top Layer w0.305: C20.1 C20.1@83.305,121.989 ; SW1.2 87.708,121.631 88.011,121.934 v1(88.011,121.989) ; C2.1@89.984,121.989 C2.1 ; v1(93.218,118.618) 93.273,118.618 93.527,118.364 C5.1
  Top Layer w0.381: C20.1@83.305,121.989 v1(88.011,121.989) C2.1@89.984,121.989
  Top Layer w0.508: C18.1 108.331,119.251 v1(108.331,119.761) ; MICRO_SD1.MP4 110.223,116.411 109.652,116.982 109.652,117.084 109.55,117.186 MICRO_SD1.MP3 109.55,126.606 110.959,128.016 123.469,128.016 124.409,127.076 124.904,127.076 125.374,126.606 MICRO_SD1.MP2 MICRO_SD1.MP1 ; MICRO_SD1.CD1@123.956,115.743 124.052,115.839 124.904,115.839 125.374,116.309 MICRO_SD1.MP1 ; v1(127.508,116.713) 125.676,116.713 MICRO_SD1.MP1
  Top Layer w0.635: C21.2 82.813,119.569 83.185,119.941 C20.1
  Bottom Layer w0.254: v1(108.645,84.769) 112.627,84.769 113.792,83.604 113.792,77.756 113.643,77.607 C22.2 111.105,75.936 110.543,75.936 110.16,75.553 110.16,74.953
  Bottom Layer w0.305: v1(81.407,117.475) 81.407,118.735 C1.1 ; BT1.2 86.36,120.338 v1(88.011,121.989)
  Bottom Layer w0.508: 110.16,74.953 110.416,75.209
LCD_BLK: JP1.6 U1.40 | length 12.4
  Top Layer w0.203: JP1.6 82.296,103.886 82.296,105.918 83.628,107.25 U1.40
LCD_CS: JP1.2 U1.46 | length 18.9
  Top Layer w0.203: JP1.2 83.82,95.25 83.82,103.251 84.819,104.25 U1.46
LCD_DC: JP1.4 U1.42 | length 15.9
  Top Layer w0.203: JP1.4 83.058,99.568 83.058,104.648 84.66,106.25 U1.42
LCD_MOSI: JP1.3 U1.43 | length 17.6
  Top Layer w0.203: JP1.3 83.439,97.409 83.439,104.013 85.176,105.75 U1.43
LCD_RES: JP1.7 U1.35 | length 21.4
  Top Layer w0.203: JP1.7 80.772,104.521 81.788,105.537 81.788,112.268 83.439,113.919 89.154,113.919 90.932,112.141 91.567,112.141 91.759,111.949 91.759,110.559 U1.35
LCD_SCK: JP1.5 U1.41 | length 14.2
  Top Layer w0.203: JP1.5 82.677,101.727 82.677,105.41 84.017,106.75 U1.41
NetBT1_1: BT1.1 D2.2 | length 14.1
  Bottom Layer w0.305: D2.2 75.109,118.745 74.803,119.051 74.803,119.634 75.311,120.142 84.681,120.142 84.86,119.963 BT1.1
NetC1_2: C1.2 D1.1 D2.1 U1.6 | length 39.3
  Top Layer w0.203: v1(106.172,112.903) 106.23,112.845 106.23,112.651 106.25,112.632 U1.6
  Bottom Layer w0.203: D1.1 78.258,116.078 77.851,116.485 77.851,118.338 78.258,118.745 D2.1 79.391,118.745 80.28,119.634 82.169,119.634 82.344,119.459 82.344,119.068 C1.2 84.318,117.094 105.537,117.094 106.172,116.459 v1(106.172,112.903)
NetC5_2: C5.2 R2.1 U1.24 Y1.1 | length 12
  Top Layer w0.203: Y1.1 96.012,120.913 96.012,118.708 C5.2
  Top Layer w0.254: C5.2 96.662,118.058 96.662,115.928 R2.1 ; R2.1@96.605,115.824 96.901,115.528 96.901,114.808 97.25,114.459 U1.24
NetC6_2: C6.2 R2.2 U1.23 Y1.2 | length 12
  Top Layer w0.203: C6.2 98.806,118.708 98.806,120.913 Y1.2
  Top Layer w0.254: U1.23 97.75,114.514 97.917,114.681 97.917,115.528 R2.2@98.213,115.824 ; R2.2 R2.2@98.213,115.824 ; C6.2 98.156,118.058 98.156,115.881 R2.2@98.213,115.824
NetC18_2: C18.2 U1.8 Y2.1 | length 10.4
  Top Layer w0.203: U1.8 105.25,117.19 106.279,118.219 Y2.1
NetC19_2: C19.2 U1.9 Y2.2 | length 10.4
  Top Layer w0.203: Y2.2 103.779,118.346 104.75,117.375 U1.9
NetC21_1: C21.1 R8.2 U*.1 U*.3 | length 0.4
  Top Layer w0.381: U*.1@78.321,123.063 78.387,122.997 U*.1
NetJP2_3: JP2.3 R15.2 | length 3.9
  Top Layer w0.305: JP2.3 122.428,78.867 123.825,78.867 124.714,79.756 R15.2@125.73,79.756
NetJP2_5: JP2.5 R16.2 | length 5.3
  Top Layer w0.305: JP2.5 123.444,81.407 124.079,82.042 124.079,83.185 124.983,84.089 R16.2
NetMICRO_SD1_5: MICRO_SD1.5 R9.2 | length 9.2
  Top Layer w0.203: MICRO_SD1.5 119.556,112.727 122.003,110.28 124.455,110.28 R9.2
NetP1_3: P1.3 R4.2 | length 3.3
  Top Layer w0.152: P1.3 86.881,81.293 87.516,81.293 88.703,82.48 88.83,82.48 R4.2
NetP1_4: P1.4 R5.1 | length 3.3
  Top Layer w0.152: R5.1 81.858,82.492 82.608,82.492 P1.4
"OV D0 PC0": "camera socket.8" U1.26 | length 39.3
  Top Layer w0.254: U1.26 96.25,109.109 v1@97.409,107.95
  Bottom Layer w0.254: v1@97.409,107.95 97.409,107.224 96.139,105.954 96.139,86.736 100.84,82.035 100.84,78.419 102.54,76.719 102.54,74.953
  other v1: 97.409,107.823
"OV D1 PC 1": "camera socket.9" U1.27 | length 32
  Top Layer w0.254: U1.27 95.75,108.281 96.012,108.019 v1@96.012,107.95
  Bottom Layer w0.254: v1@96.012,107.95 96.012,107.08 95.631,106.699 95.631,86.614 99.617,82.628 99.617,80.986 100,80.603
  other v1: 96.054,107.823
"OV D2 PC2": "camera socket.10" U1.28 | length 37.1
  Top Layer w0.254: v1@94.615,107.823 95.25,108.458 U1.28
  Bottom Layer w0.254: v1@94.615,107.823 95.123,107.315 95.123,86.36 98.806,82.677 98.806,77.554 99.949,76.411 99.949,75.946
  other v1: 94.7,107.823
"OV D3 PC3": "camera socket.11" U1.29 | length 32.3
  Top Layer w0.254: v1(93.345,107.823) 94.741,109.219 94.741,110.541 U1.29
  Bottom Layer w0.254: v1(93.345,107.823) 93.391,107.823 94.615,106.599 94.615,84.048 97.46,81.203 97.46,80.603
"OV D4 PC4": "camera socket.12" U1.44 | length 35.7
  Top Layer w0.254: U1.44 91.465,105.25 91.752,105.537 v1(91.821,105.537)
  Bottom Layer w0.254: v1(91.821,105.537) 93.571,105.537 94.107,105.001 94.107,83.947 96.491,81.563 96.491,77.779 97.536,76.734 97.536,75.692
"OV D5 PC5": "camera socket.13" U1.45 | length 28.4
  Top Layer w0.254: U1.45 92.793,104.75 92.895,104.648 v1(92.964,104.648)
  Bottom Layer w0.254: v1(92.964,104.648) 93.599,104.013 93.599,83.058 94.712,81.945 94.712,80.811 94.92,80.603
"OV D6 PC6": "camera socket.14" U1.96 | length 58.1
  Top Layer w0.254: v1(100.203,92.71) 100.711,92.202 101.346,92.202 102.75,90.798 U1.96
  Bottom Layer w0.254: 94.92,74.953 94.92,75.391 94.537,75.774 93.574,75.774 92.806,76.542 89.414,76.542 88.646,75.774 88.646,73.787 90.068,72.365 104.75,72.365 105.918,73.533 105.918,76.554 108.814,79.449 108.814,81.425 106.934,83.304 106.934,88.679 105.017,90.596 102.317,90.596 v1(100.203,92.71)
"OV D7 PC7": "camera socket.15" U1.97 | length 58.4
  Top Layer w0.254: v1(101.6,92.71) 103.25,91.06 U1.97
  Bottom Layer w0.254: 92.38,80.603 92.38,77.875 91.454,76.949 89.246,76.949 88.157,75.86 88.157,73.442 89.646,71.953 104.973,71.953 106.424,73.404 106.424,76.347 106.426,76.349 106.426,76.487 109.22,79.281 109.22,81.661 107.34,83.541 107.34,88.847 105.007,91.181 103.129,91.181 v1(101.6,92.71)
"OV OE PG15": "camera socket.7" U1.132 | length 35.7
  Top Layer w0.254: v1(107.442,103.505) 107.95,103.505 108.705,102.75 U1.132
  Bottom Layer w0.254: 102.54,80.603 102.54,82.058 102.083,82.515 102.083,82.517 97.663,86.936 97.663,99.314 101.854,103.505 v1(107.442,103.505)
"OV RCLK PB4": "camera socket.16" U1.134 | length 60
  Top Layer w0.254: v1(107.442,106.172) 108.585,105.029 108.585,104.394 109.229,103.75 U1.134
  Bottom Layer w0.254: 92.38,74.953 92.38,74.353 93.454,73.279 103.251,73.279 103.632,73.66 103.632,76.286 101.27,78.648 101.27,82.18 96.647,86.803 96.647,100.84 101.979,106.172 v1(107.442,106.172)
"OV RRST PG14": "camera socket.5" U1.129 | length 35.7
  Top Layer w0.254: v1(107.442,102.235) 107.95,102.235 108.935,101.25 U1.129
  Bottom Layer w0.254: 105.08,80.603 105.08,81.203 104.697,81.586 103.586,81.586 102.489,82.683 102.489,82.685 98.171,87.003 98.171,98.436 101.97,102.235 v1(107.442,102.235)
"OV SCL PD3": "camera socket.4" U1.117 | length 36.8
  Top Layer w0.254: v1(106.172,92.71) 106.172,93.599 106.934,94.361 108.712,94.361 109.592,95.241 110.541,95.241 U1.117
  Bottom Layer w0.254: v1(106.172,92.71) 106.172,91.948 114.3,83.82 114.3,75.565 110.998,72.263 108.331,72.263 107.62,72.974 107.62,74.953
"OV SDA PG13": "camera socket.6" U1.128 | length 41.6
  Top Layer w0.254: v1(107.442,100.965) 107.503,100.965 107.718,100.75 U1.128
  Bottom Layer w0.254: 105.08,74.953 105.08,78.443 106.045,79.408 106.045,88.265 104.648,89.662 101.219,89.662 98.679,92.202 98.679,97.79 101.854,100.965 v1(107.442,100.965)
"OV VSYNC PA8": "camera socket.17" U1.100 | length 67.9
  Top Layer w0.254: U1.100 104.75,91.923 105.283,92.456 105.283,93.345 106.934,94.996 v1(108.458,94.996)
  Bottom Layer w0.254: 89.84,80.603 89.84,78.118 87.63,75.908 87.63,73.394 89.478,71.546 111.043,71.546 114.808,75.311 114.808,84.201 108.458,90.551 v1(108.458,94.996)
"OV WEN PB3": "camera socket.18" U1.133 | length 61.4
  Top Layer w0.254: v1(107.442,104.775) 108.958,103.259 110.541,103.259 U1.133
  Bottom Layer w0.254: 89.84,74.953 89.84,74.353 91.422,72.771 103.505,72.771 104.14,73.406 104.14,76.353 101.676,78.817 101.676,82.349 97.155,86.87 97.155,100.203 101.727,104.775 v1(107.442,104.775)
"OV WRST PD6": "camera socket.3" U1.122 | length 34
  Top Layer w0.254: v1(108.331,97.79) 108.371,97.75 U1.122
  Bottom Layer w0.254: 107.442,81.153 107.442,81.381 ; 107.62,80.603 107.237,80.986 107.237,82.247 106.528,82.956 106.528,88.417 104.756,90.189 101.454,90.189 99.187,92.456 99.187,97.155 99.822,97.79 v1(108.331,97.79) ; 107.741,80.162 107.826,80.255
RST: C2.2 R1.2 SW1.1 U1.25 | length 15.8
  Top Layer w0.203: R1.2 91.616,123.51 SW1.1 91.616,117.299 92.456,116.459 93.472,116.459 94.234,115.697 94.234,114.681 96.75,112.165 U1.25
"SDIO CMD": MICRO_SD1.3 R10.2 U1.116 | length 35.8
  Top Layer w0.203: U1.116 110.554,94.746 112.645,94.746 v1(112.649,94.742) ; MICRO_SD1.3 117.604,115.389 117.604,112.647 v1(121.412,108.839) 124.734,108.839 R10.2
  Bottom Layer w0.203: v1(112.649,94.742) 114.554,94.742 115.087,95.275 115.087,105.943 118.872,109.728 120.523,109.728 v1(121.412,108.839)
"SDIO D0": MICRO_SD1.7 R11.2 U1.98 | length 44.3
  Top Layer w0.203: v1(102.87,92.71) 103.75,91.83 U1.98 ; MICRO_SD1.7 121.508,115.389 121.508,113.253 v1(121.412,113.157) 121.412,112.903 122.936,111.379 R11.2
  Bottom Layer w0.203: v1(102.87,92.71) 106.426,96.266 113.157,96.266 114.3,97.409 114.3,106.294 118.445,110.439 120.98,110.439 121.412,110.871 v1(121.412,113.157)
"SDIO D1": MICRO_SD1.8 R12.2 U1.99 | length 42.1
  Top Layer w0.203: U1.99 104.259,89.458 104.259,92.702 v1(104.267,92.71) ; MICRO_SD1.8 122.856,113.907 123.317,113.446 v1(123.317,113.157) 123.606,113.157 123.987,112.776 R12.2
  Bottom Layer w0.203: v1(104.267,92.71) 104.325,92.768 104.325,93.022 107.188,95.885 114.046,95.885 114.681,96.52 114.681,106.172 118.593,110.084 121.895,110.084 123.317,111.506 v1(123.317,113.157)
"SDIO D2": MICRO_SD1.1 R13.2 U1.111 | length 38.9
  Top Layer w0.203: U1.111 111.712,92.25 112.268,91.694 v1(113.792,91.694) ; MICRO_SD1.1 115.156,110.777 120.269,105.664 R13.2
  Bottom Layer w0.203: v1(113.792,91.694) 114.554,91.694 116.18,93.32 116.18,105.517 117.978,107.315 v1(118.745,107.315)
"SDIO D3": MICRO_SD1.2 R14.2 U1.112 | length 36.8
  Top Layer w0.203: U1.112 110.569,92.731 112.628,92.731 v1(112.649,92.71) ; MICRO_SD1.2 116.256,111.582 v1(119.253,108.585) 120.321,107.517 124.741,107.517 125.007,107.252 R14.2
  Bottom Layer w0.203: v1(112.649,92.71) 114.554,92.71 115.824,93.98 115.824,105.664 118.687,108.527 119.195,108.527 v1(119.253,108.585)
"SDIO SCK": R9.1 U1.113 | length 33.2
  Top Layer w0.203: U1.113 111.919,93.25 112.395,93.726 v1(113.792,93.726) ; R9.1 v1(127.889,109.982)
  Bottom Layer w0.203: v1(113.792,93.726) 114.427,93.726 115.443,94.742 115.443,105.791 118.999,109.347 119.634,109.347 120.904,108.077 125.984,108.077 v1(127.889,109.982)
SWCLK: P2.2 R7.1 U1.109 | length 15.5
  Top Layer w0.203: U1.109 112.839,91.25 115.57,88.519 121.056,88.519 121.31,88.265 P2.2
  Top Layer w0.305: P2.2 123.048,88.265 124.218,89.435 R7.1
SWDIO: P2.1 R6.1 U1.105 | length 20.3
  Top Layer w0.203: U1.105 107.25,90.867 107.569,91.186 108.839,91.186 113.03,86.995 P2.1
  Top Layer w0.305: P2.1 R6.1
USART2_RX: JP2.1 U1.37 | length 65
  Top Layer w0.203: U1.37 90.767,108.75 v1(91.44,108.077) ; v1(90.424,83.058) 92.202,81.28 114.808,81.28 116.84,79.248 116.84,77.089 119.38,74.549 120.396,74.549 JP2.1
  Bottom Layer w0.203: v1@90.424,83.075 90.424,107.061 v1(91.44,108.077)
USART2_TX: JP2.8 U1.36 | length 58.3
  Top Layer w0.203: U1.36 91.269,110.531 91.269,109.391 92.456,108.204 v1(92.456,106.807) ; v1(91.948,83.058) 93.091,81.915 115.824,81.915 117.856,83.947 JP2.8
  Bottom Layer w0.203: v1(91.948,83.058) 91.948,103.505 91.059,104.394 91.059,106.045 91.821,106.807 v1(92.456,106.807)
VCC: "camera socket.1" C7.2 C8.2 C9.2 C10.2 C11.2 C12.2 C13.2 C14.2 C15.2 C16.2 C17.2 C20.2 C22.1 C23.2 D1.2 JP1.9 JP2.7 MICRO_SD1.4 P1.1 P1.2 P2.4 R1.1 R3.2 R6.2 R10.1 R11.1 R12.1 R13.1 R14.1 R15.1 R16.1 U1.17 U1.39 U1.52 U1.62 U1.72 U1.84 U1.95 U1.108 U1.121 U1.131 U1.144 U2.C U3.3 U3.7 U3.8 U*.5 | length 147
  Top Layer w0.305: U3.8 75.946,85.09 76.2,85.344 76.835,85.344 77.216,84.963 U3.7 77.216,80.264 78.486,78.994 U3.3 78.486,74.676 78.867,74.295 80.127,74.295 C23.2 81.544,75.692 v1(83.058,75.692) ; v1(81.28,114.554) 81.311,114.585 81.311,116.047 R3.2 ; C20.2 83.186,123.507 89.991,123.507 R1.1 ; v1(84.201,112.522) 84.201,110.871 85.334,109.738 C17.2 86.668,109.43 87.039,109.43 87.249,109.22 87.249,108.839 88.338,107.75 U1.39 ; v1(84.963,90.932) 86.35,90.932 C14.2 88.397,90.942 88.705,91.25 U1.72 ; v1(84.963,95.885) 85.018,95.885 85.155,96.022 C9.2 86.588,96.25 U1.62 ; v1(84.963,100.203) 85.018,100.203 85.213,100.398 86.037,100.398 C15.2 87.429,100.721 87.958,101.25 U1.52 ; U1.84 96.75,87.146 97.076,86.82 97.076,86.175 C13.2 97.653,85.598 97.653,85.656 97.722,85.724 99.186,85.724 v1(99.695,86.233) ; v1(100.203,114.554) 100.242,114.515 100.242,114.398 C16.2 101.102,112.659 100.75,112.307 U1.17 ; U1.95 102.25,88.048 102.235,88.033 102.235,87.376 102.987,86.624 C7.2 v1(104.775,85.852) ; U1.108 108.75,87.719 109.464,87.005 C11.2 111.086,84.23 111.086,83.605 v1(111.125,83.566) ; U1.121 112.181,97.25 112.457,97.526 C12.2 114.554,98.415 114.554,99.187 ; U1.131 112.41,102.25 112.639,102.479 C8.2 ; U1.144 113.617,108.75 C10.2 v1(113.665,110.363) ; v1(112.649,103.632) 112.688,103.593 112.688,103.456 C8.2 ; v1(117.221,99.187) 114.554,99.187 ; MICRO_SD1.4 118.456,113.247 118.618,113.085 v1(118.618,113.03) ; JP2.7 123.736,85.509 124.332,85.509 125.718,86.895 R6.2 126.873,86.995 127.635,86.233 127.635,83.185 ; R16.1 125.872,82.677 127.127,82.677 127.635,83.185 ; R15.1 126.858,78.344 127.635,79.121 127.635,83.185 ; R10.1 127.889,108.585 ; R12.1 126.873,112.776 127.381,112.268 ; R13.1 127.381,105.664 127.635,105.918 127.635,107.188 ; R14.1 127.635,107.188 ; R11.1 127.075,111.379 127.381,111.685 127.381,112.268 ; v1(127.635,114.3) 128.345,113.59 128.345,112.268 ; C8.2 113.988,102.156 114.379,102.156 114.554,101.981 114.554,99.187 ; 127.381,112.268 128.345,112.268 ; 127.635,107.188 127.889,107.442 127.889,108.585 ; 127.889,108.585 128.524,109.22 128.524,112.089 128.345,112.268
  Bottom Layer w0.305: v1(74.549,116.078) D1.2 ; 110.16,80.603 110.16,80.003 111.306,78.857 C22.1 112.776,81.915 v1(111.125,83.566) ; v1(117.221,99.187) 117.221,100.684 U2.C
  other v1: 86.741,123.571
VDDA: C3.1 C4.1 R3.1 U1.32 U1.33 | length 16.3
  Top Layer w0.203: R3.1 89.936,116.078 C4.1 91.059,114.915 C3.1 91.059,112.776 91.313,112.522 92.202,112.522 92.75,111.974 ; U1.33 92.75,111.974 ; U1.32 93.25,111.855 93.131,111.974 92.75,111.974
pads on no net: "camera socket.MH1" "camera socket.MH2" JP1.1 JP2.4 JP2.6 MICRO_SD1. SW1.H1 U1.1 U1.2 U1.3 U1.4 U1.5 U1.7 U1.10 U1.11 U1.12 U1.13 U1.14 U1.15 U1.18 U1.19 U1.20 U1.21 U1.22 U1.34 U1.49 U1.50 U1.53 U1.54 U1.55 U1.56 U1.57 U1.58 U1.59 U1.60 U1.63 U1.64 U1.65 U1.66 U1.67 U1.68 U1.69 U1.70 U1.77 U1.78 U1.79 U1.80 U1.81 U1.82 U1.85 U1.86 U1.87 U1.88 U1.89 U1.90 U1.91 U1.92 U1.93 U1.101 U1.102 U1.103 U1.104 U1.106 U1.110 U1.114 U1.115 U1.118 U1.119 U1.123 U1.124 U1.125 U1.126 U1.127 U1.135 U1.139 U1.140 U1.141 U1.142 U2.1 U2.2 U2.3 U2.4 U2.5 U2.6 U*.4
copper on no net:
  other v2: 126.619,73.406 73.66,126.492

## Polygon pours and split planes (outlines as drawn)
GND on GND (split plane): 128.434,129.432 128.706,129.32 128.95,129.157 129.157,128.95 129.32,128.706 129.432,128.434 129.49,128.147 129.49,128 129.49,72 129.49,71.853 129.432,71.566 129.32,71.294 129.157,71.05 128.95,70.843 128.706,70.68 128.434,70.568 128.147,70.51 71.853,70.51 71.566,70.568 71.294,70.68 71.05,70.843 70.843,71.05 70.68,71.294 70.568,71.566 70.51,71.853 70.51,72 70.51,128 70.51,128.147 70.568,128.434 70.68,128.706 70.843,128.95 71.05,129.157 71.294,129.32 71.566,129.432 71.853,129.49 128.147,129.49
VCC on PWR (split plane): 128.434,129.432 128.706,129.32 128.95,129.157 129.157,128.95 129.32,128.706 129.432,128.434 129.49,128.147 129.49,128 129.49,72 129.49,71.853 129.432,71.566 129.32,71.294 129.157,71.05 128.95,70.843 128.706,70.68 128.434,70.568 128.147,70.51 71.853,70.51 71.566,70.568 71.294,70.68 71.05,70.843 70.843,71.05 70.68,71.294 70.568,71.566 70.51,71.853 70.51,72 70.51,128 70.51,128.147 70.568,128.434 70.68,128.706 70.843,128.95 71.05,129.157 71.294,129.32 71.566,129.432 71.853,129.49 128.147,129.49

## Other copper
Top Layer:
  rectangle net VCC: 80.899,123.063 83.693,123.952
  rectangle net VCC: 80.899,122.682 82.296,123.952
  rectangle net GND: 78.105,121.666 83.693,122.428
  rectangle net NetC21_1: 76.708,120.523 79.375,121.412
  rectangle net NetC21_1: 76.708,120.523 77.47,123.571
  rectangle net NetC21_1: 76.708,122.682 79.375,123.571

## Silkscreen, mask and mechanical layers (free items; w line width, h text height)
Mechanical 1:
  the board outline again, w0.254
